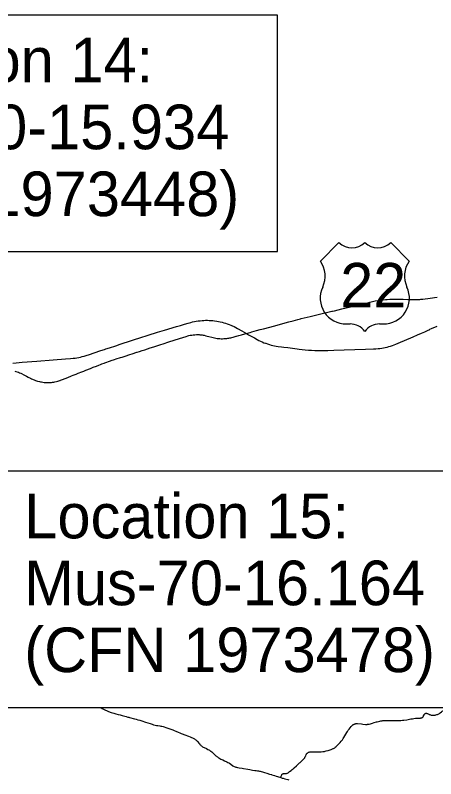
# Model space of a CAD drawing. Extents: x 1761803 to 2441803, y 509895 to 949895.
# Drawn here: x 2141149 to 2167570, y 786865 to 834796 of the extents above; entities that cross this region are included whole.
import ezdxf

# ---------------------------------------------------------------- set-up
doc = ezdxf.new("R2010")
doc.units = 0
for name, color, linetype in [('GM_X_County_Road_Text', 7, 'Continuous'), ('GM_X_Minor_Lake', 7, 'Continuous'), ('GM_X_Minor_River', 7, 'Continuous'), ('GM_X_Minor_River_Text', 7, 'Continuous'), ('GM_X_State_Location', 7, 'Continuous')]:
    doc.layers.add(name, color=color, linetype=linetype)

msp = doc.modelspace()

# ---------------------------------------------------------------- linework, layer by layer
at = {"layer": 'GM_X_County_Road_Text'}
for p, q in [((2161489, 820521), (2160329, 819361)), ((2165898, 819361), (2164738, 820521)), ((2161953, 815416), (2162185, 815416)), ((2164042, 815416), (2164274, 815416))]:
    msp.add_line(p, q, dxfattribs=at)
for centre, radius, start, end in [((2162301, 821349), 1160, 225.573, 314.427), ((2163926, 821349), 1160, 225.573, 314.427), ((2158999, 818429), 1624, 334.5471, 35.0009), ((2167228, 818429), 1624, 144.9991, 205.4529), ((2161935, 817040), 1624, 154.8319, 270.6383), ((2164292, 817040), 1624, 269.3617, 25.1681), ((2162185, 814256), 1160, 36.8699, 90), ((2164042, 814256), 1160, 90, 143.1301)]:
    msp.add_arc(centre, radius, start, end, dxfattribs=at)
at = {"layer": 'GM_X_Minor_Lake'}
for points in [[(2146529, 791334), (2146557, 791315), (2146613, 791281), (2146656, 791256), (2146728, 791219), (2146817, 791177), (2146879, 791149), (2146921, 791129), (2147011, 791089), (2147072, 791065), (2147118, 791048), (2147180, 791029), (2147338, 790984), (2147464, 790948), (2147622, 790905), (2147749, 790870), (2147859, 790840), (2148112, 790771), (2148223, 790740), (2148288, 790722), (2148334, 790710), (2148635, 790632), (2148746, 790603), (2148856, 790572), (2148967, 790540), (2149107, 790495), (2149341, 790418), (2149622, 790326), (2149746, 790286), (2149841, 790259), (2149936, 790235), (2150032, 790214), (2150080, 790205), (2150112, 790199), (2150242, 790177), (2150303, 790165), (2150354, 790155), (2150435, 790138), (2150498, 790121), (2150608, 790087), (2150733, 790046), (2150919, 789983), (2150981, 789961), (2151043, 789938), (2151134, 789902), (2151239, 789856), (2151388, 789787), (2151493, 789742), (2151584, 789705), (2151875, 789596), (2151967, 789562), (2152044, 789533), (2152136, 789498), (2152228, 789462), (2152288, 789437), (2152333, 789416), (2152376, 789391), (2152417, 789364), (2152457, 789335), (2152495, 789302), (2152530, 789268), (2152575, 789220), (2152717, 789061), (2152750, 789024), (2152784, 788989), (2152820, 788955), (2152844, 788934), (2152882, 788904), (2152923, 788877), (2152965, 788852), (2153023, 788822), (2153156, 788757), (2153259, 788707), (2153318, 788677), (2153360, 788652), (2153402, 788625), (2153441, 788595), (2153492, 788553), (2153650, 788410), (2153759, 788311), (2153799, 788277), (2153809, 788268), (2153850, 788235), (2153898, 788196), (2153939, 788170), (2153995, 788137), (2154068, 788099), (2154185, 788042), (2154290, 787994), (2154439, 787926), (2154513, 787889), (2154571, 787858), (2154613, 787833), (2154695, 787777), (2154828, 787682), (2154869, 787657), (2154912, 787634), (2154957, 787614), (2155003, 787597), (2155050, 787584), (2155114, 787570), (2155210, 787552), (2155404, 787520), (2155501, 787504), (2155760, 787458), (2155889, 787436), (2156066, 787404), (2156196, 787384), (2156277, 787374), (2156375, 787366), (2156411, 787362)], [(2157833, 786941), (2157840, 786960), (2157865, 787027), (2157882, 787073), (2157894, 787104), (2157900, 787119), (2157908, 787134), (2157918, 787148), (2157928, 787158), (2157937, 787166), (2157944, 787170), (2157952, 787174), (2157959, 787178), (2157975, 787183), (2157991, 787187), (2158008, 787189), (2158024, 787191), (2158054, 787192), (2158070, 787192), (2158086, 787192), (2158118, 787193), (2158151, 787195), (2158183, 787198), (2158199, 787201), (2158229, 787209), (2158237, 787212), (2158260, 787220), (2158300, 787245), (2158340, 787272), (2158391, 787312), (2158481, 787383), (2158557, 787445), (2158607, 787487), (2158668, 787541), (2158814, 787673), (2158908, 787759), (2158967, 787814), (2158990, 787835), (2159015, 787859), (2159051, 787892), (2159149, 787989), (2159228, 788060), (2159262, 788095), (2159295, 788130), (2159316, 788155), (2159334, 788181), (2159351, 788208), (2159373, 788251), (2159399, 788310), (2159431, 788385), (2159447, 788414), (2159456, 788429), (2159465, 788442), (2159476, 788455), (2159487, 788467), (2159502, 788480), (2159523, 788495), (2159552, 788512), (2159584, 788528), (2159619, 788540), (2159651, 788549), (2159685, 788553), (2159729, 788556), (2159797, 788557), (2160010, 788560), (2160158, 788561), (2160369, 788564), (2160467, 788568), (2160532, 788573), (2160580, 788581), (2160628, 788591), (2160691, 788607), (2160801, 788641), (2161003, 788707), (2161080, 788735), (2161125, 788754), (2161155, 788768), (2161182, 788785), (2161222, 788813), (2161260, 788846), (2161308, 788889), (2161420, 789000), (2161560, 789147), (2161619, 789214), (2161644, 789243), (2161668, 789271), (2161702, 789316), (2161748, 789385), (2161794, 789461), (2161920, 789669), (2161978, 789759), (2162021, 789827), (2162074, 789910), (2162132, 789985), (2162197, 790064), (2162261, 790139), (2162301, 790182), (2162336, 790218), (2162360, 790240), (2162387, 790260), (2162415, 790278), (2162444, 790294), (2162459, 790300), (2162491, 790311), (2162523, 790319), (2162556, 790325), (2162589, 790327), (2162648, 790327), (2162903, 790304), (2162999, 790295), (2163162, 790280), (2163220, 790277), (2163254, 790277), (2163290, 790281), (2163295, 790281), (2163338, 790288), (2163386, 790298), (2163465, 790319), (2163591, 790354), (2163701, 790387), (2163843, 790428), (2163890, 790441), (2163970, 790460), (2164050, 790477), (2164115, 790490), (2164195, 790505), (2164244, 790513), (2164284, 790519), (2164350, 790523), (2164415, 790523), (2164489, 790522), (2164621, 790522), (2164768, 790520), (2164899, 790520), (2165014, 790521), (2165096, 790522), (2165243, 790524), (2165292, 790525), (2165374, 790528), (2165472, 790536), (2165569, 790547), (2165748, 790573), (2165922, 790602), (2166005, 790618), (2166103, 790634), (2166201, 790648), (2166297, 790659), (2166365, 790664), (2166494, 790668), (2166560, 790672), (2166609, 790677), (2166641, 790682), (2166672, 790690), (2166687, 790696), (2166702, 790702), (2166716, 790709), (2166729, 790717), (2166740, 790725), (2166753, 790736), (2166765, 790747), (2166777, 790761), (2166794, 790787), (2166810, 790815), (2166838, 790874), (2166853, 790900), (2166865, 790918), (2166875, 790930), (2166885, 790942), (2166900, 790951), (2166914, 790960), (2166933, 790967), (2166948, 790971), (2166963, 790974), (2166983, 790974), (2167002, 790971), (2167020, 790966), (2167048, 790956), (2167094, 790935), (2167131, 790918)], [(2167131, 790918), (2167153, 790908), (2167198, 790889), (2167245, 790874), (2167292, 790863), (2167341, 790856), (2167389, 790853), (2167438, 790853), (2167487, 790857), (2167536, 790864), (2167583, 790874), (2167630, 790888), (2167677, 790904), (2167722, 790923), (2167765, 790945), (2167807, 790970), (2167847, 790998), (2167924, 791059), (2167975, 791099), (2168016, 791128), (2168058, 791155), (2168101, 791178), (2168147, 791198), (2168235, 791232)], [(2156411, 787362), (2156424, 787360), (2156489, 787350), (2156537, 787341), (2156601, 787325), (2156680, 787303), (2156805, 787264), (2156961, 787215), (2157133, 787160), (2157247, 787125), (2157274, 787116), (2157429, 787067), (2157538, 787033), (2157773, 786960), (2157833, 786941)], [(2157833, 786941), (2157929, 786911), (2157991, 786892), (2158085, 786864), (2158271, 786808), (2158333, 786789)]]:
    msp.add_lwpolyline(points, dxfattribs=at)
at = {"layer": 'GM_X_Minor_River'}
msp.add_lwpolyline([(2141004, 812964), (2141204, 812980), (2141593, 813011), (2142509, 813081), (2143539, 813160), (2144308, 813219), (2144618, 813244), (2144782, 813259), (2144912, 813274), (2145026, 813292), (2145139, 813313), (2145252, 813337), (2145363, 813365), (2145489, 813402), (2145677, 813461), (2145754, 813486), (2146534, 813744), (2146757, 813816), (2146846, 813845), (2147080, 813922), (2147469, 814053), (2147750, 814143), (2149163, 814610), (2149307, 814657), (2149635, 814762), (2149964, 814864), (2150093, 814903), (2150530, 815033), (2151286, 815253), (2151538, 815325), (2151790, 815399), (2152011, 815463), (2152184, 815512), (2152296, 815540), (2152408, 815564), (2152520, 815585), (2152634, 815603), (2152764, 815620), (2152894, 815632), (2153008, 815640), (2153107, 815644), (2153221, 815644), (2153336, 815640), (2153450, 815634), (2153564, 815624), (2153678, 815611), (2153808, 815593), (2153921, 815573), (2154033, 815550), (2154145, 815523), (2154256, 815493), (2154365, 815460), (2154474, 815423), (2154582, 815384), (2154688, 815341), (2154768, 815306), (2154793, 815295), (2154897, 815247), (2154999, 815195), (2155115, 815133), (2155386, 814980), (2155669, 814820), (2155814, 814737), (2156172, 814535), (2156358, 814432), (2156460, 814379), (2156549, 814336), (2156654, 814290), (2156776, 814240), (2156880, 814202), (2156884, 814200), (2156993, 814163), (2157118, 814125), (2157229, 814094), (2157341, 814066), (2157437, 814045), (2157550, 814024), (2157664, 814007), (2157878, 813980), (2158022, 813962), (2158282, 813928), (2158868, 813853), (2158991, 813839), (2159178, 813817), (2159373, 813798), (2159570, 813781), (2159766, 813769), (2159979, 813759), (2160176, 813753), (2160373, 813751), (2160570, 813752), (2160800, 813756), (2161161, 813768), (2161816, 813792), (2163161, 813835), (2163652, 813852), (2163816, 813859), (2163947, 813869), (2164062, 813881), (2164176, 813896), (2164289, 813915), (2164402, 813937), (2164514, 813962), (2164625, 813991), (2164736, 814023), (2164845, 814059), (2164953, 814098), (2165060, 814140), (2165212, 814203), (2166142, 814614), (2166429, 814736), (2166684, 814846), (2166880, 814932), (2167044, 815006), (2167193, 815075), (2167209, 815083), (2167312, 815130), (2167657, 815283)], dxfattribs=at)
at = {"layer": 'GM_X_Minor_River_Text'}
for points in [[(2162333, 816518), (2162657, 816595), (2163012, 816681), (2163153, 816715), (2163192, 816725), (2163374, 816770)], [(2163374, 816770), (2163422, 816782), (2163594, 816825), (2163756, 816860), (2163951, 816897), (2164121, 816921), (2164276, 816939), (2164419, 816951), (2164447, 816954), (2164528, 816959), (2164692, 816967), (2164840, 816970), (2164971, 816969), (2165251, 816967), (2165531, 816963), (2165811, 816961), (2166150, 816956), (2166258, 816958)], [(2166258, 816958), (2166278, 816959), (2166362, 816958), (2166502, 816959), (2166563, 816961), (2166627, 816964)], [(2166627, 816964), (2166657, 816965), (2166767, 816973), (2166908, 816987), (2167072, 817005), (2167218, 817025), (2167365, 817046), (2167495, 817069), (2167656, 817100)], [(2155037, 814646), (2155052, 814650), (2155203, 814692), (2155361, 814736), (2155567, 814792), (2155669, 814820), (2155899, 814882), (2156020, 814916), (2156167, 814957), (2156310, 814995), (2156547, 815060), (2156753, 815114), (2157149, 815222), (2157374, 815283), (2157450, 815304), (2158099, 815480), (2158330, 815542), (2158621, 815622), (2158905, 815698), (2159062, 815737), (2159117, 815751), (2159685, 815891), (2160260, 816026), (2161049, 816214), (2161075, 816220), (2161200, 816250), (2161440, 816306), (2161663, 816360), (2161950, 816428), (2162325, 816516), (2162333, 816518)], [(2141121, 812455), (2141193, 812435), (2141271, 812411), (2141348, 812383), (2141424, 812352), (2141498, 812318), (2141732, 812199), (2141848, 812138), (2141950, 812086), (2142009, 812056), (2142103, 812007), (2142170, 811975), (2142229, 811947), (2142268, 811931), (2142335, 811902), (2142412, 811873), (2142483, 811849), (2142553, 811829), (2142664, 811801), (2142727, 811787), (2142790, 811774), (2142887, 811759), (2142969, 811749), (2143051, 811742), (2143133, 811738), (2143215, 811738), (2143297, 811741), (2143346, 811743), (2143395, 811746), (2143428, 811748), (2143493, 811755), (2143559, 811765), (2143575, 811767), (2143582, 811769), (2143639, 811780), (2143736, 811802), (2143815, 811823), (2143878, 811842), (2143948, 811866), (2143969, 811874), (2143999, 811885), (2144109, 811927), (2144293, 811999), (2144460, 812065), (2144679, 812152), (2144795, 812198), (2144979, 812270), (2145101, 812319), (2145330, 812409), (2145451, 812458), (2145497, 812476), (2145589, 812512), (2145879, 812626), (2146046, 812694), (2146244, 812773), (2146397, 812832), (2146504, 812875), (2146595, 812910), (2146733, 812963), (2146782, 812981), (2146841, 813003), (2147073, 813082), (2147229, 813133), (2147322, 813164), (2147556, 813241), (2147696, 813286), (2147759, 813305), (2147868, 813340), (2148056, 813399), (2148357, 813496), (2148493, 813541), (2148782, 813635), (2148804, 813642), (2148960, 813692), (2149117, 813743), (2149288, 813798), (2149631, 813910), (2149865, 813987), (2150037, 814042), (2150305, 814129), (2150440, 814171), (2150795, 814284), (2151467, 814503), (2151889, 814638), (2151983, 814666), (2152062, 814686), (2152143, 814703), (2152239, 814719), (2152321, 814729), (2152435, 814739), (2152535, 814746), (2152570, 814747), (2152632, 814748), (2152701, 814747), (2152755, 814743), (2152820, 814737), (2152883, 814729), (2152956, 814716), (2153013, 814704), (2153130, 814679), (2153209, 814658), (2153304, 814633), (2153511, 814581), (2153751, 814527), (2153844, 814512), (2153930, 814502), (2154012, 814496), (2154094, 814492), (2154176, 814492), (2154252, 814494), (2154275, 814495), (2154395, 814504), (2154445, 814508), (2154498, 814515), (2154556, 814524), (2154562, 814525), (2154627, 814539), (2154693, 814553), (2154899, 814607), (2155037, 814646)]]:
    msp.add_lwpolyline(points, dxfattribs=at)
at = {"layer": 'GM_X_State_Location'}
for points in [[(2128253, 819961), (2157629, 819961), (2157629, 834796), (2128253, 834796)], [(2140551, 791334), (2169928, 791334), (2169928, 806169), (2140551, 806169)]]:
    msp.add_lwpolyline(points, close=True, dxfattribs=at)

# ---------------------------------------------------------------- texts
at = {"layer": 'GM_X_County_Road_Text'}
msp.add_text('22', height=2784.4, dxfattribs=at).set_placement((2161572, 816460))
at = {"layer": 'GM_X_State_Location'}
for s, p in [('Location 14:', (2129416, 830585)), ('Mus-70-15.934', (2129416, 826385)), ('(CFN 1973448)', (2129416, 822185)), ('Location 15:', (2141715, 801958)), ('Mus-70-16.164', (2141715, 797758)), ('(CFN 1973478)', (2141715, 793558))]:
    msp.add_text(s, height=2800, dxfattribs=at).set_placement(p)

doc.saveas('drawing.dxf')
